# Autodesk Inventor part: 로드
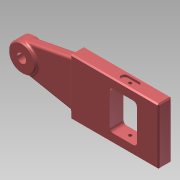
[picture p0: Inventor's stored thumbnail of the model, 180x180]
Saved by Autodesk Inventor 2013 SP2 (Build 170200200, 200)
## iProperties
Created: 2025-04
Part Number: 로드
Material: Generic
Document SubType Name: Modeling
Designer: i
Density: 1 g/cm^3
변환 표준: STEP AP214IS
전처리기: Build: 200, Release: 2013 SP2 Update 6 - Date: Thu 07/17/2014
전송 단위: 밀리미터
불확실성: 0.01
Author: i
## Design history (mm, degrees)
node "로드1"
node "솔리드1"
node "기준1"
